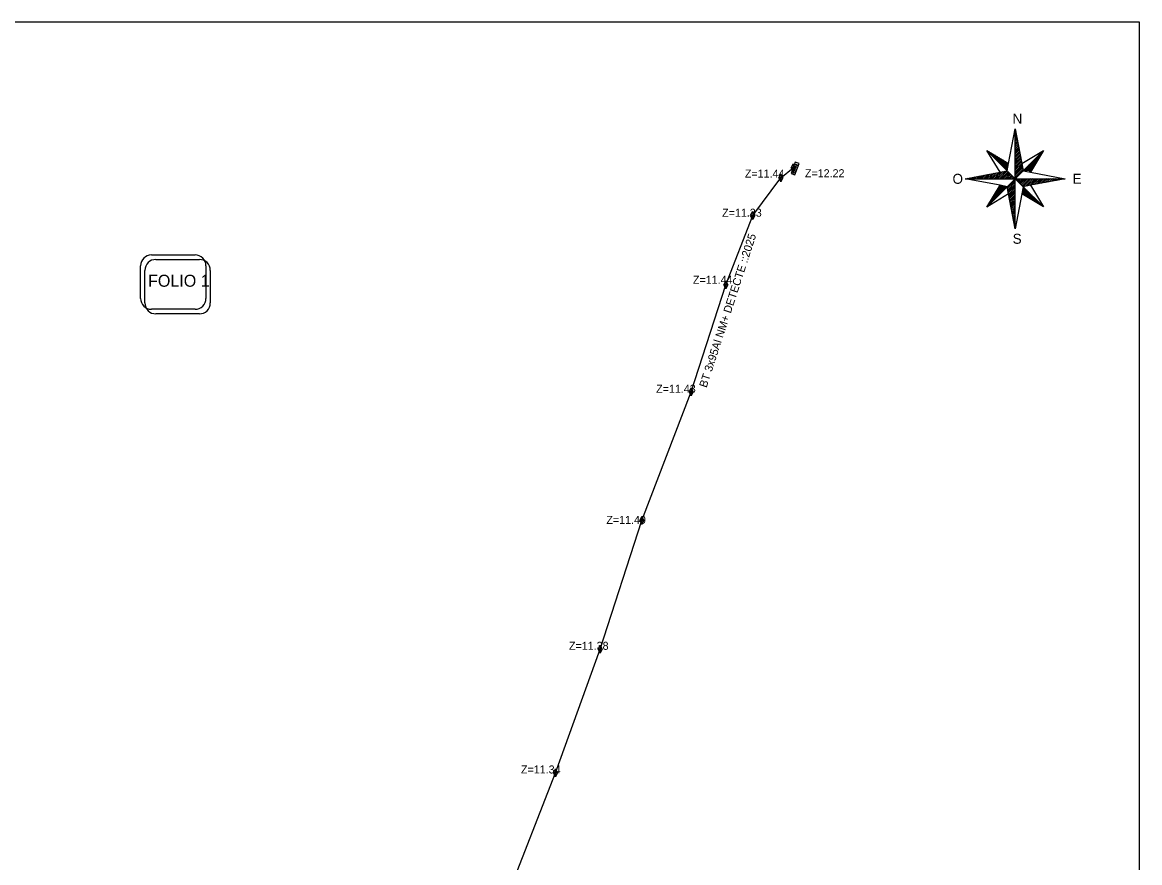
# Model space of a CAD drawing. Extents: x 376946 to 377047, y 296637 to 296721.
# Drawn here: x 376991.3 to 377047.1, y 296679.1 to 296721.1 of the extents above; entities that cross this region are included whole.
import ezdxf

# ---------------------------------------------------------------- set-up
doc = ezdxf.new("R2010")
doc.units = 0
for name, color, linetype in [('PGOC_BT_CONSTRUIT', 7, 'Continuous'), ('PGOC_HABILLAGE_PGOC', 7, 'Continuous'), ('PGOC_PTRL', 7, 'Continuous'), ('Plan_Cartouches', 7, 'Continuous'), ('Plan_Etiquette', 7, 'Continuous')]:
    doc.layers.add(name, color=color, linetype=linetype)

msp = doc.modelspace()

# ---------------------------------------------------------------- linework, layer by layer
at = {"layer": 'PGOC_BT_CONSTRUIT'}
msp.add_lwpolyline([(377029.883, 296714.115), (377029.673, 296713.553), (377029.86, 296713.483), (377030.071, 296714.045)], close=True, dxfattribs=at)
for points in [[(377015.327, 296655.971), (377014.364, 296656.533), (377012.15, 296658.888), (377010.355, 296661.19), (377010.173, 296661.529), (377010.27, 296661.958), (377010.808, 296663.561), (377011.751, 296666.226), (377013.407, 296671.561), (377015.487, 296677.397), (377017.901, 296683.591), (377020.143, 296689.776), (377022.225, 296696.206), (377024.682, 296702.64), (377026.423, 296707.991), (377027.756, 296711.46), (377029.162, 296713.33), (377029.778, 296713.834)], [(377029.727, 296713.64), (377029.876, 296713.584)], [(377029.762, 296713.733), (377029.912, 296713.677)], [(377029.78, 296713.555), (377029.963, 296714.042)], [(377029.797, 296713.827), (377029.947, 296713.771)], [(377029.832, 296713.921), (377029.982, 296713.864)], [(377029.867, 296714.014), (377030.017, 296713.958)]]:
    msp.add_lwpolyline(points, dxfattribs=at)
at = {"layer": 'PGOC_HABILLAGE_PGOC'}
msp.add_lwpolyline([(376987.689, 296721.108), (376987.689, 296637.108), (377047.089, 296637.108), (377047.089, 296721.108)], close=True, dxfattribs=at)
at = {"layer": 'PGOC_PTRL'}
for points in [[(377029.678, 296713.834), (377029.778, 296714.034), (377029.878, 296713.834), (377029.778, 296713.634), (377029.678, 296713.834)], [(377029.878, 296713.834), (377029.778, 296713.834), (377029.678, 296713.834)], [(377029.778, 296714.034), (377029.778, 296713.634)], [(377029.062, 296713.33), (377029.162, 296713.53), (377029.262, 296713.33), (377029.162, 296713.13), (377029.062, 296713.33)], [(377029.262, 296713.33), (377029.162, 296713.33), (377029.062, 296713.33)], [(377029.162, 296713.53), (377029.162, 296713.13)], [(377027.656, 296711.46), (377027.756, 296711.66), (377027.856, 296711.46), (377027.756, 296711.26), (377027.656, 296711.46)], [(377027.856, 296711.46), (377027.756, 296711.46), (377027.656, 296711.46)], [(377027.756, 296711.66), (377027.756, 296711.26)], [(377026.323, 296707.991), (377026.423, 296708.191), (377026.523, 296707.991), (377026.423, 296707.791), (377026.323, 296707.991)], [(377026.523, 296707.991), (377026.423, 296707.991), (377026.323, 296707.991)], [(377026.423, 296708.191), (377026.423, 296707.791)], [(377024.582, 296702.64), (377024.682, 296702.84), (377024.782, 296702.64), (377024.682, 296702.44), (377024.582, 296702.64)], [(377024.782, 296702.64), (377024.682, 296702.64), (377024.582, 296702.64)], [(377024.682, 296702.84), (377024.682, 296702.44)], [(377022.125, 296696.206), (377022.225, 296696.406), (377022.325, 296696.206), (377022.225, 296696.006), (377022.125, 296696.206)], [(377022.225, 296696.406), (377022.225, 296696.006)], [(377022.325, 296696.206), (377022.225, 296696.206), (377022.125, 296696.206)], [(377020.043, 296689.776), (377020.143, 296689.976), (377020.243, 296689.776), (377020.143, 296689.576), (377020.043, 296689.776)], [(377020.243, 296689.776), (377020.143, 296689.776), (377020.043, 296689.776)], [(377020.143, 296689.976), (377020.143, 296689.576)], [(377017.801, 296683.591), (377017.901, 296683.791), (377018.001, 296683.591), (377017.901, 296683.391), (377017.801, 296683.591)], [(377018.001, 296683.591), (377017.901, 296683.591), (377017.801, 296683.591)], [(377017.901, 296683.791), (377017.901, 296683.391)]]:
    msp.add_lwpolyline(points, dxfattribs=at)
at = {"layer": 'Plan_Cartouches'}
for p, q in [((377040.542, 296714.052), (377040.87, 296715.792)), ((377040.874, 296713.292), (377040.87, 296715.792)), ((377040.87, 296715.792), (377041.202, 296714.052)), ((377040.874, 296715.768), (377040.87, 296715.764)), ((377040.89, 296715.692), (377040.87, 296715.672)), ((377040.906, 296715.62), (377040.87, 296715.584)), ((377040.918, 296715.544), (377040.87, 296715.5)), ((377040.934, 296715.472), (377040.87, 296715.408)), ((377040.946, 296715.396), (377040.87, 296715.32)), ((377040.962, 296715.32), (377040.87, 296715.232)), ((377040.974, 296715.248), (377040.87, 296715.144)), ((377040.114, 296713.62), (377039.458, 296714.704)), ((377039.458, 296714.704), (377040.542, 296714.052)), ((377039.458, 296714.704), (377040.474, 296713.692)), ((377039.478, 296714.696), (377039.47, 296714.696)), ((377040.99, 296715.172), (377040.874, 296715.056)), ((377041.006, 296715.1), (377040.874, 296714.968)), ((377041.018, 296715.024), (377040.874, 296714.88)), ((377041.034, 296714.952), (377040.874, 296714.792)), ((377041.046, 296714.876), (377040.874, 296714.7)), ((377041.058, 296714.8), (377040.874, 296714.612)), ((377041.074, 296714.728), (377040.874, 296714.528)), ((377041.086, 296714.652), (377040.874, 296714.436)), ((377041.202, 296714.052), (377042.286, 296714.708)), ((377041.27, 296713.692), (377042.286, 296714.708)), ((377042.286, 296714.708), (377041.634, 296713.62)), ((377042.282, 296714.696), (377042.278, 296714.696)), ((377039.578, 296714.636), (377039.53, 296714.636)), ((377039.682, 296714.572), (377039.594, 296714.572)), ((377039.786, 296714.508), (377039.654, 296714.508)), ((377039.89, 296714.444), (377039.718, 296714.444)), ((377039.994, 296714.384), (377039.782, 296714.384)), ((377040.098, 296714.32), (377039.842, 296714.32)), ((377040.202, 296714.26), (377039.906, 296714.256)), ((377040.306, 296714.196), (377039.966, 296714.196)), ((377040.41, 296714.132), (377040.03, 296714.132)), ((377041.098, 296714.58), (377040.874, 296714.348)), ((377041.114, 296714.504), (377040.874, 296714.26)), ((377041.13, 296714.432), (377040.874, 296714.172)), ((377041.146, 296714.356), (377040.874, 296714.084)), ((377041.158, 296714.28), (377040.874, 296713.996)), ((377041.174, 296714.208), (377040.874, 296713.904)), ((377041.186, 296714.132), (377040.874, 296713.82)), ((377041.942, 296714.136), (377041.714, 296714.136)), ((377041.982, 296714.196), (377041.778, 296714.2)), ((377042.018, 296714.26), (377041.838, 296714.26)), ((377042.054, 296714.32), (377041.902, 296714.32)), ((377042.094, 296714.384), (377041.962, 296714.384)), ((377042.13, 296714.448), (377042.026, 296714.448)), ((377042.166, 296714.508), (377042.086, 296714.508)), ((377042.206, 296714.572), (377042.15, 296714.572)), ((377042.242, 296714.636), (377042.214, 296714.636)), ((377038.374, 296713.288), (377040.114, 296713.62)), ((377039.714, 296713.544), (377039.462, 296713.292)), ((377039.826, 296713.564), (377039.55, 296713.292)), ((377039.934, 296713.584), (377039.638, 296713.292)), ((377040.046, 296713.608), (377039.726, 296713.292)), ((377040.154, 296713.628), (377039.814, 296713.292)), ((377040.262, 296713.652), (377039.902, 296713.292)), ((377040.374, 296713.672), (377039.994, 296713.292)), ((377040.478, 296713.688), (377040.082, 296713.292)), ((377040.514, 296714.072), (377040.094, 296714.072)), ((377040.114, 296713.62), (377040.474, 296713.692)), ((377040.534, 296714.008), (377040.158, 296714.008)), ((377040.522, 296713.644), (377040.166, 296713.292)), ((377040.522, 296713.944), (377040.222, 296713.944)), ((377040.566, 296713.6), (377040.258, 296713.292)), ((377040.514, 296713.884), (377040.282, 296713.884)), ((377040.502, 296713.82), (377040.346, 296713.82)), ((377040.606, 296713.556), (377040.346, 296713.292)), ((377040.486, 296713.76), (377040.406, 296713.76)), ((377040.478, 296713.696), (377040.47, 296713.696)), ((377040.474, 296713.692), (377040.542, 296714.052)), ((377040.474, 296713.692), (377040.874, 296713.292)), ((377041.202, 296714.06), (377040.874, 296713.728)), ((377041.214, 296713.984), (377040.874, 296713.64)), ((377041.23, 296713.912), (377040.874, 296713.552)), ((377041.242, 296713.836), (377040.874, 296713.464)), ((377041.258, 296713.76), (377040.874, 296713.376)), ((377040.874, 296713.292), (377041.27, 296713.692)), ((377041.202, 296714.052), (377041.27, 296713.692)), ((377041.27, 296713.692), (377041.634, 296713.62)), ((377041.682, 296713.696), (377041.278, 296713.696)), ((377041.718, 296713.76), (377041.342, 296713.76)), ((377041.754, 296713.824), (377041.402, 296713.82)), ((377041.794, 296713.888), (377041.466, 296713.884)), ((377041.83, 296713.948), (377041.526, 296713.948)), ((377041.642, 296713.632), (377041.566, 296713.632)), ((377041.866, 296714.008), (377041.59, 296714.008)), ((377041.634, 296713.62), (377043.374, 296713.292)), ((377041.906, 296714.072), (377041.654, 296714.072)), ((377038.374, 296713.288), (377040.874, 296713.292)), ((377040.114, 296712.964), (377038.374, 296713.288)), ((377038.406, 296713.3), (377038.402, 296713.292)), ((377038.518, 296713.316), (377038.49, 296713.292)), ((377038.626, 296713.336), (377038.578, 296713.288)), ((377038.734, 296713.36), (377038.666, 296713.288)), ((377038.842, 296713.38), (377038.754, 296713.288)), ((377038.954, 296713.4), (377038.842, 296713.288)), ((377039.062, 296713.424), (377038.93, 296713.288)), ((377039.17, 296713.444), (377039.022, 296713.288)), ((377039.282, 296713.464), (377039.11, 296713.292)), ((377039.39, 296713.484), (377039.194, 296713.292)), ((377039.498, 296713.504), (377039.286, 296713.292)), ((377039.606, 296713.524), (377039.374, 296713.292)), ((377040.654, 296713.512), (377040.434, 296713.292)), ((377040.474, 296712.892), (377040.874, 296713.292)), ((377040.874, 296713.288), (377040.474, 296712.892)), ((377040.874, 296713.2), (377040.49, 296712.82)), ((377040.874, 296713.112), (377040.506, 296712.744)), ((377040.874, 296713.024), (377040.518, 296712.668)), ((377040.698, 296713.464), (377040.522, 296713.292)), ((377040.742, 296713.42), (377040.61, 296713.292)), ((377040.786, 296713.38), (377040.702, 296713.292)), ((377040.83, 296713.332), (377040.79, 296713.292)), ((377040.874, 296713.292), (377040.874, 296713.288)), ((377040.874, 296713.292), (377041.27, 296712.892)), ((377040.874, 296713.292), (377043.374, 296713.292)), ((377040.874, 296710.792), (377040.874, 296713.292)), ((377040.966, 296713.292), (377040.918, 296713.248)), ((377041.054, 296713.292), (377040.962, 296713.2)), ((377041.142, 296713.292), (377041.006, 296713.156)), ((377041.23, 296713.292), (377041.05, 296713.112)), ((377041.318, 296713.292), (377041.094, 296713.068)), ((377041.406, 296713.292), (377041.142, 296713.028)), ((377041.494, 296713.292), (377041.186, 296712.98)), ((377041.582, 296713.292), (377041.23, 296712.936)), ((377041.67, 296713.296), (377041.274, 296712.896)), ((377041.762, 296713.296), (377041.386, 296712.916)), ((377041.846, 296713.292), (377041.494, 296712.936)), ((377041.934, 296713.292), (377041.602, 296712.96)), ((377043.374, 296713.292), (377041.634, 296712.964)), ((377042.026, 296713.292), (377041.71, 296712.98)), ((377042.114, 296713.292), (377041.822, 296712.996)), ((377042.202, 296713.292), (377041.93, 296713.02)), ((377042.29, 296713.292), (377042.038, 296713.04)), ((377042.378, 296713.292), (377042.15, 296713.06)), ((377042.47, 296713.296), (377042.254, 296713.08)), ((377042.554, 296713.296), (377042.366, 296713.1)), ((377042.642, 296713.296), (377042.474, 296713.124)), ((377042.734, 296713.296), (377042.582, 296713.144)), ((377042.822, 296713.296), (377042.694, 296713.164)), ((377042.91, 296713.292), (377042.802, 296713.188)), ((377042.998, 296713.292), (377042.91, 296713.204)), ((377043.086, 296713.292), (377043.018, 296713.224)), ((377043.174, 296713.292), (377043.126, 296713.248)), ((377043.262, 296713.292), (377043.238, 296713.268)), ((377043.35, 296713.292), (377043.346, 296713.288)), ((377039.458, 296711.876), (377040.114, 296712.964)), ((377039.458, 296711.876), (377040.474, 296712.892)), ((377040.542, 296712.532), (377039.458, 296711.876)), ((377040.026, 296712.444), (377039.802, 296712.444)), ((377040.09, 296712.508), (377039.842, 296712.508)), ((377040.154, 296712.572), (377039.878, 296712.572)), ((377040.214, 296712.632), (377039.914, 296712.632)), ((377040.278, 296712.696), (377039.954, 296712.696)), ((377040.342, 296712.76), (377039.99, 296712.76)), ((377040.402, 296712.82), (377040.03, 296712.82)), ((377040.466, 296712.884), (377040.066, 296712.884)), ((377040.202, 296712.944), (377040.102, 296712.944)), ((377040.474, 296712.892), (377040.114, 296712.964)), ((377040.542, 296712.532), (377040.474, 296712.892)), ((377040.874, 296712.932), (377040.534, 296712.596)), ((377040.874, 296710.792), (377040.542, 296712.532)), ((377040.874, 296712.848), (377040.55, 296712.52)), ((377040.874, 296712.76), (377040.558, 296712.444)), ((377040.874, 296712.668), (377040.574, 296712.372)), ((377040.874, 296712.58), (377040.59, 296712.3)), ((377040.874, 296712.492), (377040.602, 296712.224)), ((377041.202, 296712.532), (377040.874, 296710.792)), ((377041.27, 296712.892), (377041.202, 296712.532)), ((377042.29, 296711.88), (377041.202, 296712.532)), ((377041.598, 296712.572), (377041.21, 296712.572)), ((377041.534, 296712.632), (377041.222, 296712.632)), ((377041.47, 296712.696), (377041.234, 296712.696)), ((377041.658, 296712.508), (377041.242, 296712.508)), ((377041.41, 296712.76), (377041.246, 296712.76)), ((377041.346, 296712.82), (377041.258, 296712.82)), ((377041.634, 296712.964), (377041.27, 296712.892)), ((377041.27, 296712.892), (377042.29, 296711.88)), ((377041.282, 296712.884), (377041.27, 296712.884)), ((377041.718, 296712.448), (377041.342, 296712.448)), ((377041.634, 296712.964), (377042.29, 296711.88)), ((377039.466, 296711.884), (377039.462, 296711.884)), ((377039.53, 296711.948), (377039.502, 296711.944)), ((377039.59, 296712.012), (377039.538, 296712.012)), ((377039.654, 296712.072), (377039.578, 296712.072)), ((377039.714, 296712.132), (377039.614, 296712.132)), ((377039.774, 296712.196), (377039.65, 296712.196)), ((377039.838, 296712.256), (377039.69, 296712.256)), ((377039.902, 296712.32), (377039.726, 296712.32)), ((377039.962, 296712.384), (377039.762, 296712.384)), ((377040.874, 296712.404), (377040.618, 296712.148)), ((377040.874, 296712.316), (377040.63, 296712.076)), ((377040.874, 296712.224), (377040.646, 296712)), ((377040.874, 296712.14), (377040.658, 296711.924)), ((377040.874, 296712.052), (377040.674, 296711.852)), ((377040.874, 296711.96), (377040.69, 296711.78)), ((377040.874, 296711.872), (377040.702, 296711.7)), ((377041.782, 296712.388), (377041.446, 296712.384)), ((377041.842, 296712.32), (377041.55, 296712.32)), ((377041.906, 296712.26), (377041.654, 296712.26)), ((377041.97, 296712.196), (377041.758, 296712.2)), ((377042.03, 296712.136), (377041.862, 296712.136)), ((377042.094, 296712.072), (377041.966, 296712.072)), ((377042.158, 296712.008), (377042.07, 296712.008)), ((377042.218, 296711.948), (377042.174, 296711.948)), ((377042.282, 296711.884), (377042.278, 296711.884)), ((377040.874, 296711.784), (377040.718, 296711.624)), ((377040.874, 296711.696), (377040.73, 296711.552)), ((377040.874, 296711.608), (377040.742, 296711.48)), ((377040.874, 296711.52), (377040.758, 296711.404)), ((377040.874, 296711.432), (377040.77, 296711.328)), ((377040.874, 296711.344), (377040.786, 296711.256)), ((377040.874, 296711.252), (377040.798, 296711.18)), ((377040.874, 296711.168), (377040.814, 296711.104)), ((377040.874, 296711.08), (377040.83, 296711.032)), ((377040.874, 296710.988), (377040.842, 296710.96)), ((377040.874, 296710.9), (377040.858, 296710.884)), ((377040.874, 296710.812), (377040.87, 296710.808))]:
    msp.add_line(p, q, dxfattribs=at)
at = {"layer": 'Plan_Etiquette'}
for points in [[(376997.724, 296709.484), (376999.899, 296709.484)], [(376997.942, 296709.255), (377000.117, 296709.255)], [(376997.18, 296707.31), (376997.18, 296708.941)], [(376997.398, 296707.08), (376997.398, 296708.712)], [(377000.443, 296708.941), (377000.443, 296707.31)], [(377000.661, 296708.712), (377000.661, 296707.08)], [(376999.899, 296706.766), (376997.724, 296706.766)], [(377000.117, 296706.537), (376997.942, 296706.537)]]:
    msp.add_lwpolyline(points, dxfattribs=at)
for centre, start, end in [((376997.724, 296708.941), 90, 180), ((376997.942, 296708.712), 90, 180), ((376999.899, 296708.941), 0, 90), ((377000.117, 296708.712), 0, 90), ((376997.724, 296707.31), 180, 270), ((376997.942, 296707.08), 180, 270), ((376999.899, 296707.31), 270, 0), ((377000.117, 296707.08), 270, 0)]:
    msp.add_arc(centre, 0.544, start, end, dxfattribs=at)

# ---------------------------------------------------------------- texts
at = {"layer": 'PGOC_BT_CONSTRUIT'}
msp.add_text('BT 3x95Al NM+ DETECTE ::2025', height=0.4, rotation=71.9779, dxfattribs=at).set_placement((377025.451, 296702.821))
at = {"layer": 'PGOC_PTRL'}
for s, p in [('Z=11.44', (377027.367, 296713.35)), ('Z=12.22', (377030.366, 296713.366)), ('Z=11.33', (377026.231, 296711.392)), ('Z=11.44', (377024.771, 296708.04)), ('Z=11.43', (377022.933, 296702.592)), ('Z=11.49', (377020.446, 296696.04)), ('Z=11.38', (377018.579, 296689.746)), ('Z=11.34', (377016.18, 296683.566))]:
    msp.add_text(s, height=0.4, dxfattribs=at).set_placement(p)
at = {"layer": 'Plan_Cartouches'}
for s, p in [('N', (377040.742, 296716.04)), ('O', (377037.742, 296713.036)), ('E', (377043.742, 296713.04)), ('S', (377040.746, 296710.04))]:
    msp.add_text(s, height=0.5, rotation=0.0297, dxfattribs=at).set_placement(p)
at = {"layer": 'Plan_Etiquette'}
msp.add_text('FOLIO 1', height=0.6, dxfattribs=at).set_placement((376997.551, 296707.892))

doc.saveas('drawing.dxf')
